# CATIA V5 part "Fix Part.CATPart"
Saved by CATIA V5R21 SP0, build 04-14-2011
Part number: Part4
Bounding box of the stored display mesh (mm): x -100 to 100, y -60 to 60, z -30 to 80.884
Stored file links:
  E:\cadcim\Projects\CATIA Resources\CATIA V5-6R2014_partfiles\Partfiles\c16_catia_v5_6r2014_prt\Rack Joint(Fig16-57)\Fix Part.CATPart
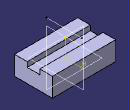
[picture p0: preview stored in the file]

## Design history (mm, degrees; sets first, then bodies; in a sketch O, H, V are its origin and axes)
Body1 (main body)
  Sketch1 on yz-plane, origin (0, 0, 0), H (0, 1, 0), V (0, 0, 1)
    line L1 (60, 30) -> (60, -30)
    line L2 (60, -30) -> (-60, -30)
    line L3 (-60, -30) -> (-60, 30)
    point P1 (60, 30)
    point P4 (-60, 30)
    point P5 (20, 30)
    line L4 (-20, 30) -> (-20, 14.3569)
    line L5 (-20, 14.3569) -> (20, 14.3569)
    line L6 (20, 14.3569) -> (20, 30)
    point P6 (-20, 30)
    point P7 (-20, 14.3569)
    point P8 (20, 14.3569)
    reference intersected line E1 through (0, 0) direction (-1, 0) from xy-plane
    reference intersected line E3 through (0, 0) direction (0, 1) from zx-plane
    line L7 (20, 30) -> (60, 30)
    line L8 (-20, 30) -> (-60, 30)
    reference intersected line E4 through (0, 0) direction (-1, 0) from xy-plane
    reference intersected line E6 through (0, 0) direction (0, 1) from zx-plane
    distance H L2 = 30
    distance V L1 = 60
    distance E1 L5 = 14.3569
    distance L4 L6 = 40
    distance P7 E3 = 20
    distance P5 P8 = 15.6431
    vertical: L1 V, L3 V, L4 V, L6 V, E3 V, E6 V
    horizontal: L2 H, L5 H, E1 H, L7 H, L8 H, E4 H
    equidistance: L1 L3 O
    perpendicularity: E1 L1
    coincidence: P1 L8, P4 L7, P5 L8, P6 L7, L7 L8
  Pad1: profile Sketch1, direction (1, 0, 0), length 100, mirrored extent
  Sketch2 on yz-plane, origin (0, 0, 0), H (0, 1, 0), V (0, 0, 1)
    line L1 (52.4742, 80.8837) -> (-58.5645, 80.8837)
    point P1 (52.4742, 80.8837)
    point P2 (-58.5645, 80.8837)
    distance P1 P2 = 111.0387
    horizontal: L1 H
